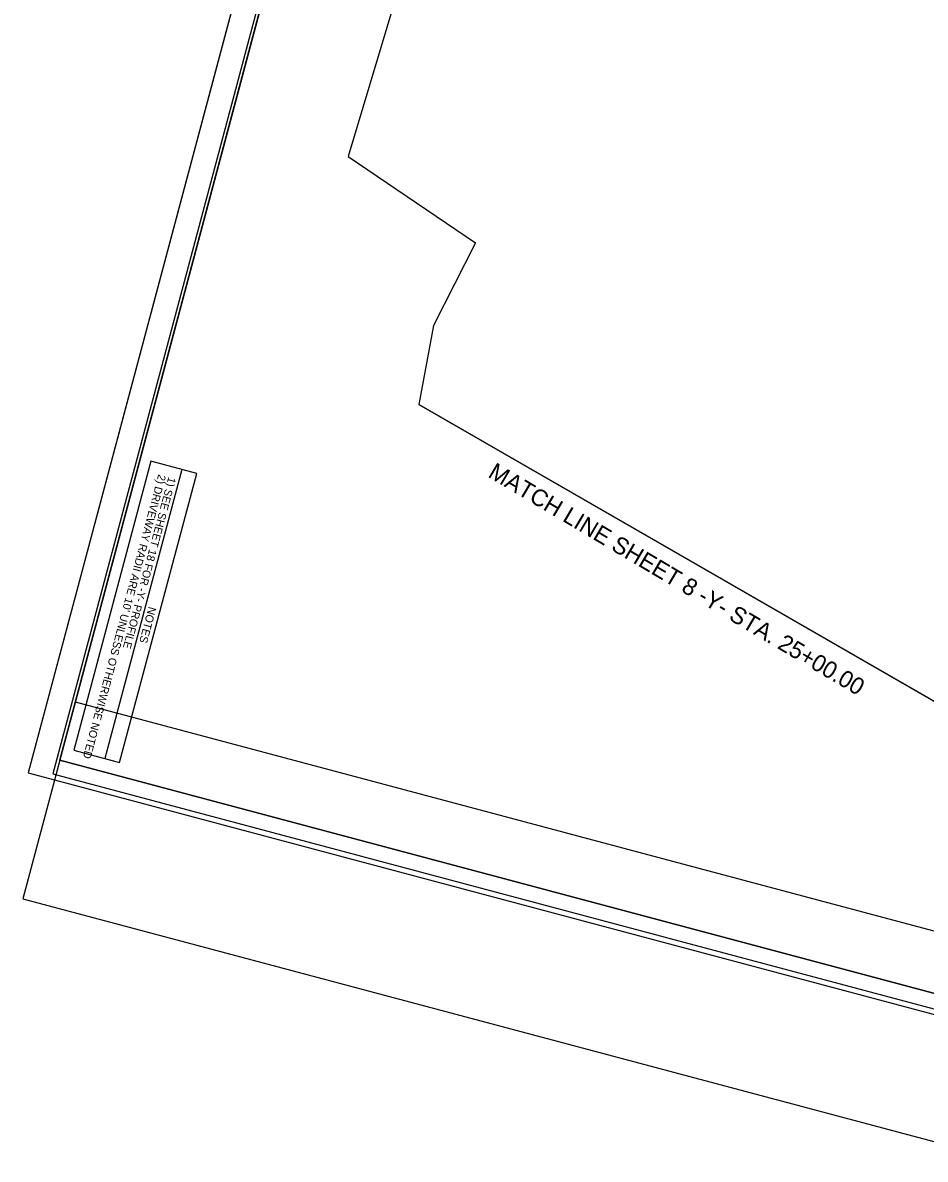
# Model space of a CAD drawing. Extents: x 1782179 to 1783675, y 813964 to 816136.
# Drawn here: x 1782179 to 1782927, y 814107 to 815050 of the extents above; entities that cross this region are included whole.
import ezdxf

# ---------------------------------------------------------------- set-up
doc = ezdxf.new("R2010")
doc.units = 0
for name, color, linetype in [('Matchline', 7, 'Continuous'), ('Matchline Text', 7, 'Continuous'), ('Prop DSN Text', 7, 'Continuous'), ('Prop Grid Mask', 7, 'Continuous'), ('Sheet Clip Boundary CELL', 7, 'Continuous'), ('Sheet Cutting Line CELL', 7, 'Continuous'), ('Sheet Layout Plan Border', 7, 'Continuous'), ('Sheet Plan CELL', 7, 'Continuous'), ('Sheet Plan Layout CELL', 7, 'Continuous'), ('Sheet Plot Border Inside CELL', 7, 'Continuous'), ('Sheet Plot Border Outside CELL', 7, 'Continuous')]:
    doc.layers.add(name, color=color, linetype=linetype)

msp = doc.modelspace()

# ---------------------------------------------------------------- linework, layer by layer
at = {"layer": 'Matchline'}
msp.add_line((1783008.64, 814444.36), (1782507.47, 814733.25), dxfattribs=at)
at = {"layer": 'Prop Grid Mask'}
for points in [[(1782285.27, 814686.12), (1782221.4, 814446.61), (1782259.4, 814436.47), (1782323.27, 814675.98)], [(1782310.87, 814679.29), (1782247, 814439.78), (1782259.4, 814436.47), (1782323.27, 814675.98)]]:
    msp.add_lwpolyline(points, close=True, dxfattribs=at)
at = {"layer": 'Sheet Clip Boundary CELL'}
msp.add_lwpolyline([(1782607.14, 815866.45), (1782558.93, 815688.64), (1782520.27, 815177.89), (1782448.76, 814938.83), (1782554.29, 814867.24), (1782519.56, 814798.86), (1782507.47, 814733.25), (1783124.85, 814377.38), (1783147.7, 814463.07), (1783193.89, 814449.44), (1783239.39, 814501.8), (1783298.45, 814452.34), (1783593.62, 815603.37)], close=True, dxfattribs=at)
at = {"layer": 'Sheet Cutting Line CELL'}
msp.add_line((1782617.37, 816054.32), (1782183.56, 814427.67), dxfattribs=at)
at = {"layer": 'Sheet Layout Plan Border'}
for points in [[(1782596.22, 815887.65), (1782209.69, 814438.29), (1783019.88, 814222.22), (1783071.43, 814415.52), (1783275.79, 814361.02), (1783610.77, 815617.08)], [(1782583.33, 815839.34), (1782222.57, 814486.61), (1783032.77, 814270.53), (1783081.54, 814453.41), (1783285.88, 814398.91), (1783597.87, 815568.77)]]:
    msp.add_lwpolyline(points, close=True, dxfattribs=at)
at = {"layer": 'Sheet Plan CELL'}
for points in [[(1783224.22, 814167.7), (1783610.76, 815617.08), (1782596.22, 815887.65), (1782209.69, 814438.29)], [(1782596.22, 815887.65), (1783610.74, 815617.11), (1783275.79, 814361.02), (1783130.79, 814399.67), (1783079.23, 814206.39), (1782209.69, 814438.29)]]:
    msp.add_lwpolyline(points, close=True, dxfattribs=at)
at = {"layer": 'Sheet Plan Layout CELL'}
for points in [[(1783610.74, 815617.11), (1782596.22, 815887.65), (1782209.69, 814438.31), (1783019.89, 814222.23), (1783081.54, 814453.41), (1783285.88, 814398.91)], [(1783580.1, 815502.23), (1782565.58, 815772.77), (1782179.05, 814323.42), (1782989.25, 814107.35), (1783050.9, 814338.52), (1783255.25, 814284.02)]]:
    msp.add_lwpolyline(points, close=True, dxfattribs=at)
at = {"layer": 'Sheet Plot Border Inside CELL'}
msp.add_lwpolyline([(1782633.34, 816036.6), (1782204.06, 814426.87), (1783223.41, 814155.01), (1783652.71, 815764.74)], close=True, dxfattribs=at)
at = {"layer": 'Sheet Plot Border Outside CELL'}
msp.add_lwpolyline([(1782617.37, 816054.32), (1782183.56, 814427.67), (1783241.58, 814145.51), (1783675.39, 815772.15)], close=True, dxfattribs=at)

# ---------------------------------------------------------------- texts
at = {"layer": 'Matchline Text'}
msp.add_text('MATCH LINE SHEET 8 -Y- STA. 25+00.00', height=14, rotation=329.35951, dxfattribs=at).set_placement((1782563.95, 814673.6))
at = {"layer": 'Prop DSN Text'}
for s, height, p in [("2) DRIVEWAY RADII ARE 10' UNLESS OTHERWISE NOTED", 6.56, (1782291.55, 814675.73)), ('1) SEE SHEET 18 FOR -Y- PROFILE ', 6.56, (1782299.86, 814673.51)), ('NOTES', 6.639, (1782283.47, 814566.01))]:
    msp.add_text(s, height=height, rotation=255.06728, dxfattribs=at).set_placement(p)

doc.saveas('drawing.dxf')
